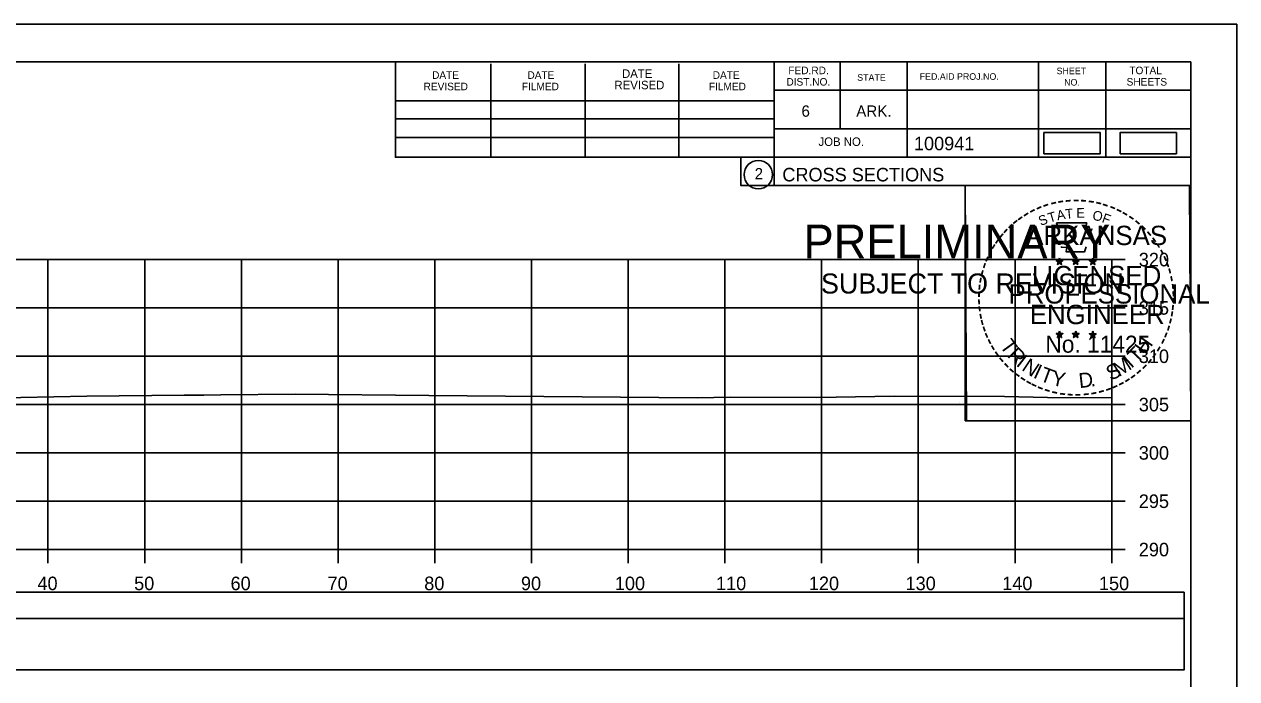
# Model space of a CAD drawing. Extents: x 1370538 to 1372872, y 376220 to 381127.
# Drawn here: x 1370746.2 to 1370871.5, y 379626.9 to 379694.6 of the extents above; entities that cross this region are included whole.
import ezdxf

# ---------------------------------------------------------------- set-up
doc = ezdxf.new("R2010")
doc.units = 0
for name, color, linetype in [('Default', 7, 'Continuous'), ('R_Border Notes', 7, 'Continuous'), ('R_Border PE', 7, 'Continuous'), ('R_Border Prem', 7, 'Continuous'), ('R_Dimension', 7, 'Continuous'), ('R_Grid', 7, 'Continuous'), ('R_No Plot', 7, 'Continuous'), ('R_Water', 7, 'Continuous'), ('T_Detection Zones', 7, 'Continuous'), ('T_Indications', 7, 'Continuous'), ('T_Notes', 7, 'Continuous')]:
    doc.layers.add(name, color=color, linetype=linetype)

msp = doc.modelspace()

# ---------------------------------------------------------------- linework, layer by layer
at = {"layer": 'Default'}
for points in [[(1370851.6, 379681.24), (1370857.43, 379681.24), (1370857.43, 379683.43), (1370851.6, 379683.43)], [(1370859.47, 379681.24), (1370865.3, 379681.24), (1370865.3, 379683.43), (1370859.47, 379683.43)]]:
    msp.add_lwpolyline(points, close=True, dxfattribs=at)
at = {"layer": 'R_Border Notes'}
for p, q in [((1370550.61, 379690.75), (1370866.79, 379690.75)), ((1370784.53, 379680.87), (1370784.53, 379690.75)), ((1370794.39, 379680.87), (1370794.39, 379690.55)), ((1370804.15, 379680.87), (1370804.15, 379690.55)), ((1370813.83, 379680.87), (1370813.83, 379690.55)), ((1370823.69, 379690.75), (1370823.69, 379677.95)), ((1370830.53, 379690.75), (1370830.53, 379683.81)), ((1370837.47, 379690.75), (1370837.47, 379680.87)), ((1370851.05, 379690.75), (1370851.05, 379680.87)), ((1370857.99, 379690.75), (1370857.99, 379680.87)), ((1370866.79, 379485.29), (1370866.79, 379690.75)), ((1370866.79, 379687.81), (1370823.69, 379687.81)), ((1370866.79, 379687.83), (1370866.79, 379687.83)), ((1370784.53, 379686.73), (1370823.69, 379686.73)), ((1370784.53, 379684.87), (1370823.69, 379684.87)), ((1370866.79, 379683.81), (1370823.69, 379683.81)), ((1370826.65, 379683.81), (1370866.79, 379683.81)), ((1370784.53, 379680.87), (1370784.53, 379682.93)), ((1370784.53, 379682.93), (1370823.69, 379682.93)), ((1370866.79, 379680.87), (1370784.53, 379680.87)), ((1370823.69, 379677.95), (1370866.79, 379677.95))]:
    msp.add_line(p, q, dxfattribs=at)
msp.add_circle((1370822.07, 379679.08), 1.47, dxfattribs=at)
at = {"layer": 'R_Border Prem'}
for p, q in [((1370858.61, 379640.29), (1370858.61, 379670.29)), ((1370860.01, 379670.29), (1370858.61, 379670.29)), ((1370860.01, 379665.29), (1370858.61, 379665.29)), ((1370860.01, 379660.29), (1370858.61, 379660.29)), ((1370860.01, 379655.29), (1370858.61, 379655.29)), ((1370860.01, 379650.29), (1370858.61, 379650.29)), ((1370860.01, 379645.29), (1370858.61, 379645.29)), ((1370558.61, 379640.29), (1370858.61, 379640.29)), ((1370748.61, 379638.89), (1370748.61, 379640.29)), ((1370758.61, 379638.89), (1370758.61, 379640.29)), ((1370768.61, 379638.89), (1370768.61, 379640.29)), ((1370778.61, 379638.89), (1370778.61, 379640.29)), ((1370788.61, 379638.89), (1370788.61, 379640.29)), ((1370798.61, 379638.89), (1370798.61, 379640.29)), ((1370808.61, 379638.89), (1370808.61, 379640.29)), ((1370818.61, 379638.89), (1370818.61, 379640.29)), ((1370828.61, 379638.89), (1370828.61, 379640.29)), ((1370838.61, 379638.89), (1370838.61, 379640.29)), ((1370848.61, 379638.89), (1370848.61, 379640.29)), ((1370858.61, 379638.89), (1370858.61, 379640.29)), ((1370860.01, 379640.29), (1370858.61, 379640.29))]:
    msp.add_line(p, q, dxfattribs=at)
at = {"layer": 'R_Dimension'}
msp.add_lwpolyline([(1370738.95, 379655.87), (1370752.62, 379656.16), (1370762.7, 379656.27), (1370764.72, 379656.28), (1370766.5, 379656.29), (1370774.17, 379656.36), (1370788, 379656.24), (1370815.74, 379655.98), (1370819.18, 379656.04), (1370828.11, 379656.02), (1370836.1, 379656.16), (1370847.53, 379656.14), (1370851.98, 379656.01), (1370858.61, 379656)], dxfattribs=at)
at = {"layer": 'R_Grid'}
for p, q in [((1370558.61, 379670.29), (1370858.61, 379670.29)), ((1370748.61, 379640.29), (1370748.61, 379670.29)), ((1370758.61, 379640.29), (1370758.61, 379670.29)), ((1370768.61, 379640.29), (1370768.61, 379670.29)), ((1370778.61, 379640.29), (1370778.61, 379670.29)), ((1370788.61, 379640.29), (1370788.61, 379670.29)), ((1370798.61, 379640.29), (1370798.61, 379670.29)), ((1370808.61, 379640.29), (1370808.61, 379670.29)), ((1370818.61, 379640.29), (1370818.61, 379670.29)), ((1370828.61, 379640.29), (1370828.61, 379670.29)), ((1370838.61, 379640.29), (1370838.61, 379670.29)), ((1370848.61, 379640.29), (1370848.61, 379670.29)), ((1370858.61, 379640.29), (1370858.61, 379670.29)), ((1370558.61, 379665.29), (1370858.61, 379665.29)), ((1370558.61, 379660.29), (1370858.61, 379660.29)), ((1370558.61, 379655.29), (1370858.61, 379655.29)), ((1370558.61, 379650.29), (1370858.61, 379650.29)), ((1370558.61, 379645.29), (1370858.61, 379645.29)), ((1370558.61, 379640.29), (1370858.61, 379640.29))]:
    msp.add_line(p, q, dxfattribs=at)
at = {"layer": 'R_No Plot'}
for p, q in [((1370538.21, 379694.64), (1370871.54, 379694.64)), ((1370842.82, 379655.49), (1370842.82, 379655.49))]:
    msp.add_line(p, q, dxfattribs=at)
for points in [[(1370538.2, 379694.64), (1370871.54, 379694.64), (1370871.54, 379481.3), (1370538.2, 379481.3)], [(1370784.53, 379690.75), (1370784.53, 379680.87), (1370820.26, 379680.87), (1370820.26, 379677.95), (1370843.46, 379677.95), (1370843.46, 379653.61), (1370866.79, 379653.61), (1370866.79, 379485.29), (1370550.61, 379485.29), (1370550.61, 379690.75)], [(1370843.46, 379677.95), (1370866.67, 379677.95), (1370866.79, 379653.61), (1370843.58, 379653.61)]]:
    msp.add_lwpolyline(points, close=True, dxfattribs=at)
at = {"layer": 'R_Water'}
msp.add_lwpolyline([(1370550.96, 379627.84), (1370866.09, 379627.84), (1370866.09, 379633.16), (1370550.96, 379633.16)], close=True, dxfattribs=at)
at = {"layer": 'T_Detection Zones'}
msp.add_lwpolyline([(1370550.96, 379633.16), (1370866.09, 379633.16), (1370866.09, 379635.87), (1370550.96, 379635.87)], close=True, dxfattribs=at)
at = {"layer": 'T_Indications'}
for p, q in [((1370852.87, 379670.2), (1370853.22, 379670.09)), ((1370852.87, 379670.2), (1370853.12, 379670.16)), ((1370852.87, 379670.2), (1370853.11, 379670.08)), ((1370853, 379669.79), (1370853.22, 379670.09)), ((1370853, 379669.79), (1370853.13, 379670.04)), ((1370853, 379669.79), (1370853.22, 379670.01)), ((1370853.22, 379670.45), (1370853.18, 379670.2)), ((1370853.22, 379670.09), (1370853.22, 379670.45)), ((1370853.22, 379670.45), (1370853.27, 379670.2)), ((1370853.57, 379670.2), (1370853.22, 379670.09)), ((1370853.43, 379669.79), (1370853.22, 379670.09)), ((1370853.43, 379669.79), (1370853.22, 379670.01)), ((1370853.57, 379670.2), (1370853.28, 379670.15)), ((1370853.43, 379669.79), (1370853.3, 379670.08)), ((1370853.57, 379670.2), (1370853.36, 379670.1)), ((1370854.54, 379670.2), (1370854.89, 379670.09)), ((1370854.54, 379670.2), (1370854.79, 379670.16)), ((1370854.54, 379670.2), (1370854.78, 379670.08)), ((1370854.67, 379669.79), (1370854.89, 379670.09)), ((1370854.67, 379669.79), (1370854.8, 379670.04)), ((1370854.67, 379669.79), (1370854.89, 379670.01)), ((1370854.89, 379670.45), (1370854.85, 379670.2)), ((1370854.89, 379670.09), (1370854.89, 379670.45)), ((1370854.89, 379670.45), (1370854.94, 379670.2)), ((1370855.24, 379670.2), (1370854.89, 379670.09)), ((1370855.1, 379669.79), (1370854.89, 379670.09)), ((1370855.1, 379669.79), (1370854.89, 379670.01)), ((1370855.24, 379670.2), (1370854.95, 379670.15)), ((1370855.1, 379669.79), (1370854.97, 379670.08)), ((1370855.24, 379670.2), (1370855.03, 379670.1)), ((1370856.31, 379670.19), (1370856.65, 379670.08)), ((1370856.31, 379670.19), (1370856.56, 379670.14)), ((1370856.31, 379670.19), (1370856.54, 379670.07)), ((1370856.44, 379669.78), (1370856.65, 379670.08)), ((1370856.44, 379669.78), (1370856.56, 379670.02)), ((1370856.44, 379669.78), (1370856.65, 379670)), ((1370856.65, 379670.44), (1370856.61, 379670.19)), ((1370856.65, 379670.08), (1370856.65, 379670.44)), ((1370856.65, 379670.44), (1370856.7, 379670.19)), ((1370857, 379670.19), (1370856.65, 379670.08)), ((1370856.87, 379669.78), (1370856.65, 379670.08)), ((1370856.87, 379669.78), (1370856.65, 379669.99)), ((1370857, 379670.19), (1370856.72, 379670.14)), ((1370856.87, 379669.78), (1370856.73, 379670.07)), ((1370857, 379670.19), (1370856.8, 379670.09)), ((1370852.87, 379662.63), (1370853.22, 379662.52)), ((1370852.87, 379662.63), (1370853.12, 379662.58)), ((1370852.87, 379662.63), (1370853.1, 379662.51)), ((1370853, 379662.22), (1370853.22, 379662.52)), ((1370853, 379662.22), (1370853.13, 379662.46)), ((1370853, 379662.22), (1370853.21, 379662.44)), ((1370853.22, 379662.88), (1370853.18, 379662.63)), ((1370853.43, 379662.22), (1370853.21, 379662.43)), ((1370853.22, 379662.52), (1370853.22, 379662.88)), ((1370853.22, 379662.88), (1370853.27, 379662.63)), ((1370853.56, 379662.63), (1370853.22, 379662.52)), ((1370853.43, 379662.22), (1370853.22, 379662.52)), ((1370853.56, 379662.63), (1370853.28, 379662.58)), ((1370853.43, 379662.22), (1370853.29, 379662.51)), ((1370853.56, 379662.63), (1370853.36, 379662.53)), ((1370854.54, 379662.63), (1370854.89, 379662.52)), ((1370854.54, 379662.63), (1370854.79, 379662.58)), ((1370854.54, 379662.63), (1370854.77, 379662.51)), ((1370854.67, 379662.22), (1370854.89, 379662.52)), ((1370854.67, 379662.22), (1370854.8, 379662.46)), ((1370854.67, 379662.22), (1370854.88, 379662.44)), ((1370854.89, 379662.88), (1370854.84, 379662.63)), ((1370855.1, 379662.22), (1370854.88, 379662.43)), ((1370854.89, 379662.52), (1370854.89, 379662.88)), ((1370854.89, 379662.88), (1370854.93, 379662.63)), ((1370855.23, 379662.63), (1370854.89, 379662.52)), ((1370855.1, 379662.22), (1370854.89, 379662.52)), ((1370855.23, 379662.63), (1370854.95, 379662.58)), ((1370855.1, 379662.22), (1370854.96, 379662.51)), ((1370855.23, 379662.63), (1370855.03, 379662.53)), ((1370856.3, 379662.62), (1370856.65, 379662.51)), ((1370856.3, 379662.62), (1370856.56, 379662.57)), ((1370856.3, 379662.62), (1370856.54, 379662.5)), ((1370856.44, 379662.21), (1370856.65, 379662.51)), ((1370856.44, 379662.21), (1370856.56, 379662.45)), ((1370856.44, 379662.21), (1370856.65, 379662.43)), ((1370856.65, 379662.87), (1370856.61, 379662.62)), ((1370856.65, 379662.51), (1370856.65, 379662.87)), ((1370856.65, 379662.87), (1370856.7, 379662.62)), ((1370857, 379662.62), (1370856.65, 379662.51)), ((1370856.87, 379662.21), (1370856.65, 379662.51)), ((1370856.87, 379662.21), (1370856.65, 379662.42)), ((1370857, 379662.62), (1370856.71, 379662.57)), ((1370856.87, 379662.21), (1370856.73, 379662.5)), ((1370857, 379662.62), (1370856.8, 379662.52))]:
    msp.add_line(p, q, dxfattribs=at)
for points in [[(1370852.91, 379674.08), (1370853.18, 379673.25)], [(1370856.42, 379673.16), (1370856.57, 379673.44), (1370855.88, 379673.42), (1370856.03, 379674.08), (1370852.91, 379674.08)], [(1370853.4, 379671.66), (1370853.4, 379671.57), (1370853.97, 379671.55), (1370853.91, 379671.08), (1370855.78, 379671.08), (1370855.98, 379671.61)], [(1370853.22, 379670.45), (1370853.43, 379669.79), (1370852.87, 379670.2), (1370853.57, 379670.2), (1370853, 379669.79), (1370853.22, 379670.45)], [(1370854.89, 379670.45), (1370855.1, 379669.79), (1370854.54, 379670.2), (1370855.24, 379670.2), (1370854.67, 379669.79), (1370854.89, 379670.45)], [(1370856.65, 379670.44), (1370856.87, 379669.78), (1370856.31, 379670.19), (1370857, 379670.19), (1370856.44, 379669.78), (1370856.65, 379670.44)], [(1370853.22, 379662.88), (1370853.43, 379662.22), (1370852.87, 379662.63), (1370853.56, 379662.63), (1370853, 379662.22), (1370853.22, 379662.88)], [(1370854.89, 379662.88), (1370855.1, 379662.22), (1370854.54, 379662.63), (1370855.23, 379662.63), (1370854.67, 379662.22), (1370854.89, 379662.88)], [(1370856.65, 379662.87), (1370856.87, 379662.21), (1370856.3, 379662.62), (1370857, 379662.62), (1370856.44, 379662.21), (1370856.65, 379662.87)]]:
    msp.add_lwpolyline(points, dxfattribs=at)
for centre, radius in [((1370853.22, 379670.09), 0.172), ((1370853.22, 379670.09), 0.145), ((1370853.22, 379670.09), 0.116), ((1370853.22, 379670.09), 0.0991), ((1370853.22, 379670.09), 0.0747), ((1370853.22, 379670.09), 0.0495), ((1370853.22, 379670.09), 0.0296), ((1370854.89, 379670.09), 0.172), ((1370854.89, 379670.09), 0.145), ((1370854.89, 379670.09), 0.116), ((1370854.89, 379670.09), 0.0991), ((1370854.89, 379670.09), 0.0747), ((1370854.89, 379670.09), 0.0495), ((1370854.89, 379670.09), 0.0296), ((1370856.65, 379670.08), 0.172), ((1370856.65, 379670.08), 0.145), ((1370856.65, 379670.08), 0.116), ((1370856.65, 379670.08), 0.0991), ((1370856.65, 379670.08), 0.0747), ((1370856.65, 379670.08), 0.0495), ((1370856.65, 379670.08), 0.0296), ((1370853.22, 379662.52), 0.172), ((1370853.22, 379662.52), 0.145), ((1370853.22, 379662.52), 0.116), ((1370853.22, 379662.52), 0.0991), ((1370853.22, 379662.52), 0.0747), ((1370853.22, 379662.52), 0.0495), ((1370853.22, 379662.52), 0.0296), ((1370854.88, 379662.52), 0.172), ((1370854.88, 379662.52), 0.145), ((1370854.88, 379662.52), 0.116), ((1370854.88, 379662.52), 0.0991), ((1370854.88, 379662.52), 0.0747), ((1370854.88, 379662.52), 0.0495), ((1370854.88, 379662.52), 0.0296), ((1370856.65, 379662.51), 0.172), ((1370856.65, 379662.51), 0.145), ((1370856.65, 379662.51), 0.116), ((1370856.65, 379662.51), 0.0991), ((1370856.65, 379662.51), 0.0747), ((1370856.65, 379662.51), 0.0495), ((1370856.65, 379662.51), 0.0296)]:
    msp.add_circle(centre, radius, dxfattribs=at)

# ---------------------------------------------------------------- texts
at = {"layer": 'R_Border Notes'}
for s, height, p in [('FED.RD.', 0.782, (1370825.17, 379689.47)), ('SHEET', 0.684, (1370852.91, 379689.47)), ('TOTAL', 0.782, (1370860.43, 379689.47)), ('DATE', 0.782, (1370788.33, 379688.99)), ('DATE', 0.782, (1370798.19, 379688.99)), ('REVISED', 0.879, (1370807.19, 379687.91)), ('DATE', 0.879, (1370807.97, 379689.09)), ('DATE', 0.782, (1370817.35, 379688.99)), ('DIST.NO.', 0.782, (1370824.97, 379688.29)), ('STATE', 0.684, (1370832.29, 379688.79)), ('FED.AID PROJ.NO.', 0.684, (1370838.75, 379688.89)), ('NO.', 0.684, (1370853.69, 379688.29)), ('SHEETS', 0.782, (1370860.15, 379688.29)), ('REVISED', 0.782, (1370787.45, 379687.81)), ('FILMED', 0.782, (1370797.61, 379687.81)), ('FILMED', 0.782, (1370816.95, 379687.81)), ('6', 1.17, (1370826.53, 379685.07)), ('ARK.', 1.172, (1370832.19, 379685.07)), ('JOB NO.', 0.879, (1370828.29, 379682.05)), ('100941', 1.4, (1370838.16, 379681.6)), ('2', 1.17, (1370821.69, 379678.59)), ('CROSS SECTIONS', 1.4, (1370824.55, 379678.38))]:
    msp.add_text(s, height=height, rotation=360, dxfattribs=at).set_placement(p)
at = {"layer": 'R_Border PE'}
for s, p in [('320', (1370861.41, 379669.59)), ('315', (1370861.41, 379664.59)), ('310', (1370861.41, 379659.59)), ('305', (1370861.41, 379654.59)), ('300', (1370861.41, 379649.59)), ('295', (1370861.41, 379644.59)), ('290', (1370861.41, 379639.59)), ('40', (1370747.52, 379636.09)), ('50', (1370757.52, 379636.09)), ('60', (1370767.49, 379636.09)), ('70', (1370777.52, 379636.09)), ('80', (1370787.52, 379636.09)), ('90', (1370797.52, 379636.09)), ('100', (1370807.23, 379636.09)), ('110', (1370817.69, 379636.09)), ('120', (1370827.29, 379636.09)), ('130', (1370837.29, 379636.09)), ('140', (1370847.29, 379636.09)), ('150', (1370857.29, 379636.09))]:
    msp.add_text(s, height=1.4, dxfattribs=at).set_placement(p)
at = {"layer": 'T_Indications'}
for s, height, rotation, p in [('-', 1.6, 13.6301, (1370852.41, 379675.45)), ('-', 1.6, 10.2193, (1370853.09, 379675.61)), ('-', 1.6, 5.8968, (1370853.82, 379675.72)), ('-', 1.6, 0.1862, (1370854.59, 379675.79)), ('-', 1.6, 357.743, (1370855.31, 379675.78)), ('-', 1.6, 352.1617, (1370856.06, 379675.72)), ('-', 1.6, 347.2049, (1370856.78, 379675.61)), ('-', 1.6, 34.0636, (1370849.8, 379674.25)), ('-', 1.6, 28.7918, (1370850.39, 379674.62)), ('-', 1.6, 24.3072, (1370851.03, 379674.94)), ('-', 1.6, 19.1761, (1370851.66, 379675.21)), ('T', 1, 16.4036, (1370852.18, 379674.09)), ('A', 1, 11.2132, (1370853.01, 379674.34)), ('T', 1, 6.0228, (1370853.86, 379674.5)), ('E', 1, 0.8323, (1370854.96, 379674.61)), ('O', 1, 350.4515, (1370856.57, 379674.4)), ('F', 1, 340.0707, (1370857.52, 379674.18)), ('-', 1.6, 342.3362, (1370857.41, 379675.45)), ('-', 1.6, 337.8551, (1370858.15, 379675.23)), ('-', 1.6, 334.1211, (1370858.78, 379674.96)), ('-', 1.6, 329.6409, (1370859.36, 379674.68)), ('-', 1.6, 42.9622, (1370848.31, 379673.06)), ('-', 1.6, 38.9507, (1370848.74, 379673.48)), ('-', 1.6, 36.2317, (1370849.22, 379673.85)), ('ARKANSAS', 2, 360, (1370849.77, 379671.79)), ('S', 1, 21.594, (1370851.27, 379673.76)), ('-', 1.6, 325.8627, (1370860, 379674.31)), ('-', 1.6, 320.5297, (1370860.61, 379673.89)), ('-', 1.6, 315.5786, (1370861.21, 379673.4)), ('-', 1.6, 54.2325, (1370847.05, 379671.53)), ('-', 1.6, 50.6142, (1370847.46, 379672.1)), ('-', 1.6, 48.423, (1370847.86, 379672.58)), ('-', 1.6, 309.8797, (1370861.78, 379672.85)), ('-', 1.6, 306.6522, (1370862.3, 379672.25)), ('-', 1.6, 62.8713, (1370846.41, 379670.39)), ('-', 1.6, 58.0706, (1370846.72, 379671)), ('-', 1.4, 303.6753, (1370862.79, 379671.68)), ('-', 1.6, 299.6684, (1370863.11, 379671.07)), ('-', 1.6, 72.3945, (1370845.93, 379669.15)), ('-', 1.6, 67.7743, (1370846.15, 379669.78)), ('DWB', 0.01, 360, (1370853.21, 379670.08)), ('DWB', 0.01, 360, (1370854.88, 379670.08)), ('DWB', 0.01, 360, (1370856.64, 379670.07)), ('-', 1.6, 294.6628, (1370863.43, 379670.46)), ('-', 1.6, 290.5728, (1370863.69, 379669.88)), ('-', 1.6, 75.461, (1370845.73, 379668.43)), ('LICENSED', 2, 360, (1370850.36, 379667.64)), ('-', 1.6, 285.1233, (1370863.92, 379669.3)), ('-', 1.6, 85.1863, (1370845.52, 379667.03)), ('-', 1.6, 81.2013, (1370845.6, 379667.72)), ('PROFESSIONAL', 2, 360, (1370847.94, 379665.74)), ('-', 1.6, 280.5493, (1370864.12, 379668.56)), ('-', 1.6, 276.5962, (1370864.28, 379667.79)), ('-', 1.6, 94.1959, (1370845.53, 379665.6)), ('-', 1.6, 89.0622, (1370845.5, 379666.33)), ('-', 1.6, 274.3301, (1370864.34, 379667.07)), ('-', 1.6, 269.9407, (1370864.38, 379666.44)), ('-', 1.6, 98.9479, (1370845.61, 379664.94)), ('ENGINEER', 2, 360, (1370850.13, 379663.61)), ('-', 1.6, 260.9953, (1370864.29, 379665.12)), ('-', 1.6, 263.5172, (1370864.36, 379665.77)), ('-', 1.6, 101.7149, (1370845.74, 379664.2)), ('-', 1.6, 105.4578, (1370845.9, 379663.61)), ('-', 1.6, 255.7626, (1370864.18, 379664.44)), ('-', 1.6, 109.0874, (1370846.12, 379662.98)), ('-', 1.6, 114.0643, (1370846.37, 379662.38)), ('No. 11425', 1.757, 360, (1370851.75, 379660.66)), ('DWB', 0.01, 360, (1370853.2, 379662.51)), ('DWB', 0.01, 360, (1370854.87, 379662.51)), ('DWB', 0.01, 360, (1370856.64, 379662.5)), ('-', 1.6, 247.8887, (1370863.77, 379663.05)), ('-', 1.6, 252.8681, (1370864, 379663.72)), ('-', 1.6, 115.7289, (1370846.68, 379661.76)), ('-', 1.6, 120.4471, (1370847.03, 379661.18)), ('T', 1.54, 306.0406, (1370846.98, 379661.35)), ('R', 1.54, 314.005, (1370847.74, 379660.31)), ('T', 1.54, 46.6444, (1370861.21, 379659.45)), ('H', 1.54, 54.6088, (1370862.1, 379660.39)), ('-', 1.6, 239.0712, (1370863.12, 379661.67)), ('-', 1.6, 244.6197, (1370863.51, 379662.42)), ('-', 1.6, 125.8934, (1370847.44, 379660.62)), ('-', 1.6, 130.7181, (1370847.9, 379660.06)), ('I', 1.54, 321.9694, (1370848.64, 379659.37)), ('N', 1.54, 326.5002, (1370849.21, 379658.9)), ('M', 1.54, 32.6563, (1370859.36, 379658.12)), ('I', 1.54, 42.1136, (1370860.64, 379658.97)), ('-', 1.6, 231.2538, (1370862.29, 379660.45)), ('-', 1.6, 233.8452, (1370862.72, 379661.02)), ('-', 1.6, 134.2238, (1370848.42, 379659.52)), ('-', 1.6, 138.9338, (1370848.94, 379659.05)), ('I', 1.54, 335.3603, (1370850.41, 379658.12)), ('T', 1.54, 339.8912, (1370851.08, 379657.79)), ('Y', 1.54, 347.8556, (1370852.29, 379657.34)), ('S', 1.54, 26.9312, (1370858.52, 379657.72)), ('-', 1.6, 221.0851, (1370861.28, 379659.38)), ('-', 1.6, 225.7653, (1370861.81, 379659.89)), ('-', 1.6, 144.6463, (1370849.5, 379658.65)), ('-', 1.6, 148.0898, (1370850.06, 379658.28)), ('-', 1.6, 151.5704, (1370850.64, 379657.95)), ('-', 1.6, 154.6002, (1370851.16, 379657.71)), ('D', 1.54, 6.3969, (1370855.28, 379656.99)), ('.', 1.54, 13.7642, (1370856.47, 379657.11)), ('-', 1.6, 207.3568, (1370859.64, 379658.17)), ('-', 1.6, 212.2491, (1370860.2, 379658.52)), ('-', 1.6, 215.7363, (1370860.74, 379658.9)), ('-', 1.6, 158.5612, (1370851.78, 379657.45)), ('-', 1.6, 162.7983, (1370852.47, 379657.24)), ('-', 1.6, 167.5555, (1370853.19, 379657.07)), ('-', 1.6, 173.1155, (1370853.96, 379656.96)), ('-', 1.6, 176.5183, (1370854.71, 379656.91)), ('-', 1.6, 181.5918, (1370855.45, 379656.93)), ('-', 1.6, 185.8167, (1370856.26, 379657.01)), ('-', 1.6, 191.2858, (1370856.99, 379657.14)), ('-', 1.6, 195.4743, (1370857.72, 379657.34)), ('-', 1.6, 200.7184, (1370858.4, 379657.58)), ('-', 1.6, 204.2516, (1370859.02, 379657.85))]:
    msp.add_text(s, height=height, rotation=rotation, dxfattribs=at).set_placement(p)
at = {"layer": 'T_Notes'}
for s, height, p in [('PRELIMINARY', 3.5, (1370826.74, 379670.41)), ('DWB', 0.01, (1370827.48, 379672.26)), ('SUBJECT TO REVISION', 2.0751, (1370828.55, 379666.78))]:
    msp.add_text(s, height=height, rotation=360, dxfattribs=at).set_placement(p)

doc.saveas('drawing.dxf')
